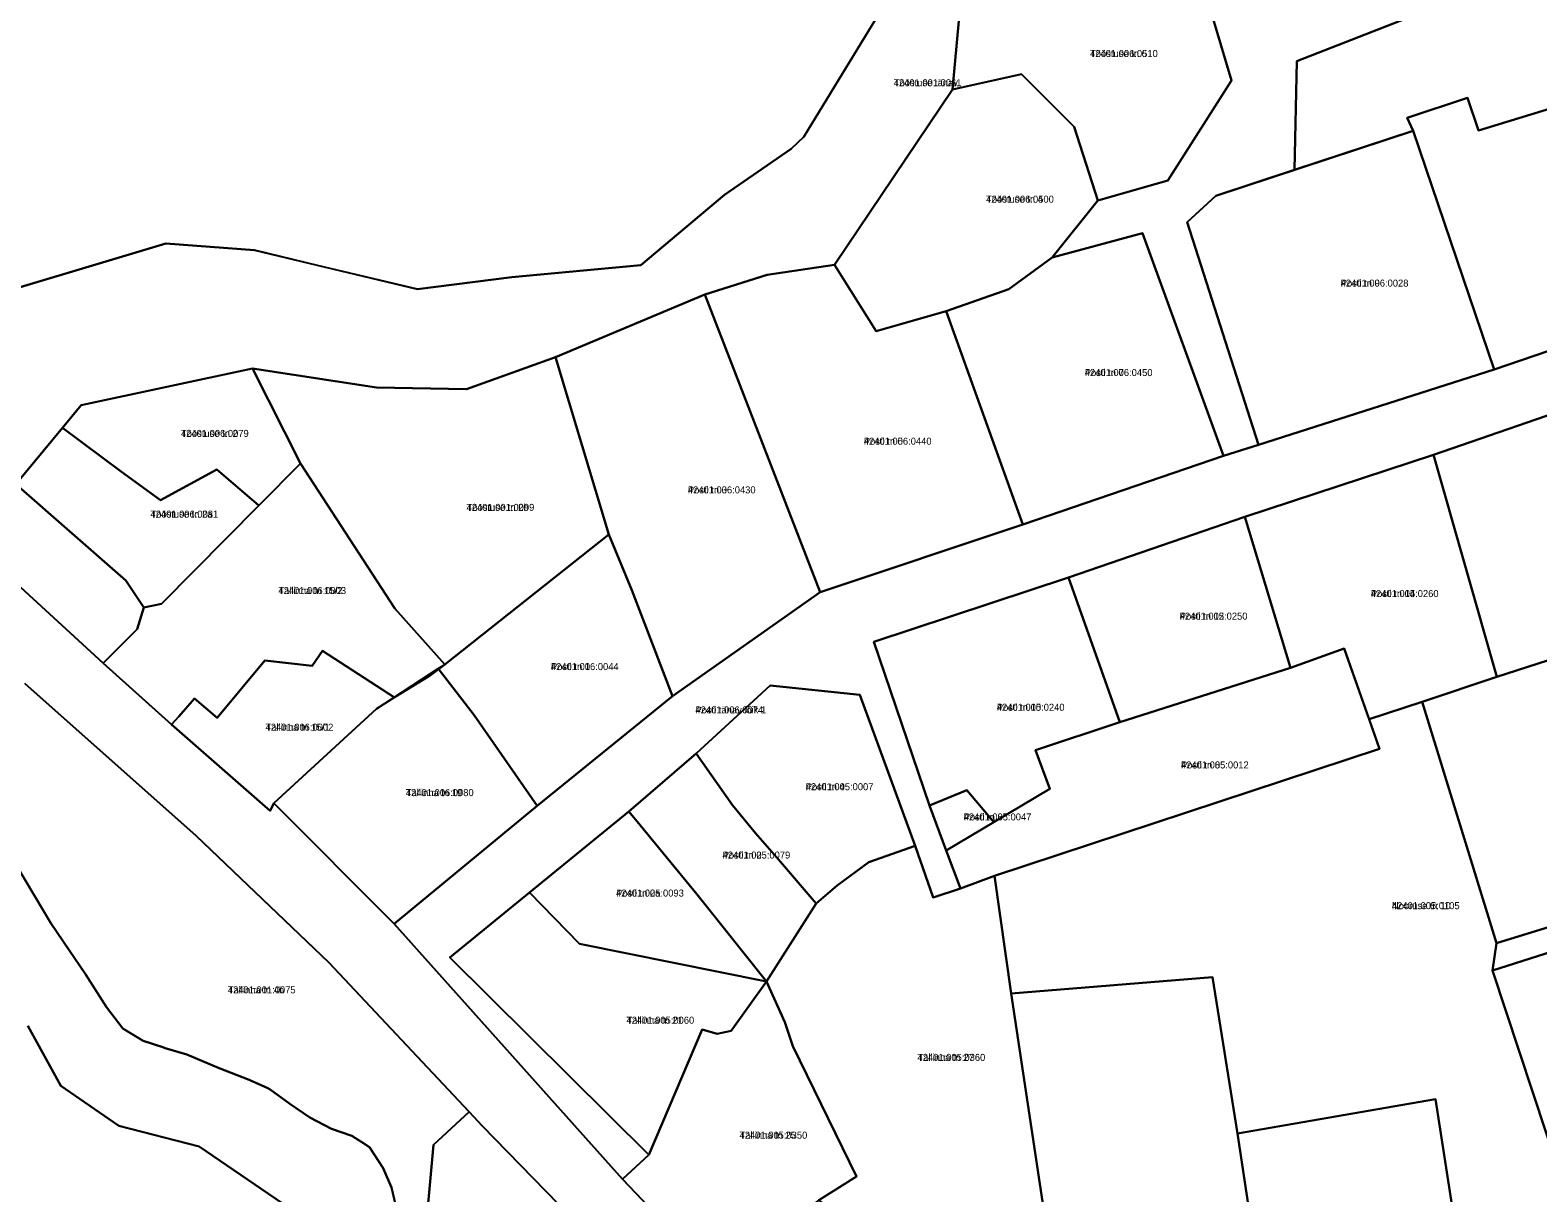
# Model space of a CAD drawing. Extents: x 595979 to 597983, y 6604231 to 6607350.
# Drawn here: x 596873.6 to 597196.3, y 6606309.2 to 6606558.1 of the extents above; entities that cross this region are included whole.
import ezdxf

# ---------------------------------------------------------------- set-up
doc = ezdxf.new("R2010")
doc.units = 0
for name, color, linetype in [('L_AADRESS', 7, 'Continuous'), ('PIIR', 7, 'Continuous'), ('TUNNUS', 7, 'Continuous')]:
    doc.layers.add(name, color=color, linetype=linetype)

msp = doc.modelspace()

# ---------------------------------------------------------------- linework, layer by layer
at = {"layer": 'PIIR'}
for points in [[(597099.55, 6606577.35), (597115.61, 6606582.36), (597120.15, 6606583.09), (597130.78, 6606547.35), (597117.1, 6606525.95), (597102.13, 6606521.61), (597097.06, 6606537.41), (597085.79, 6606548.69), (597071.01, 6606545.43), (597072.92, 6606565.63)], [(597054.66, 6606493.63), (597045.75, 6606507.88), (597071.01, 6606545.43), (597085.79, 6606548.69), (597097.06, 6606537.41), (597102.13, 6606521.61), (597092.39, 6606509.42), (597083.11, 6606502.64), (597069.66, 6606497.95)], [(597168.37, 6606539.36), (597181.28, 6606543.65), (597183.62, 6606536.59), (597214.68, 6606546.12), (597230.22, 6606500.23), (597187.03, 6606485.44), (597169.62, 6606536.56)], [(597121.24, 6606517.02), (597127.39, 6606522.61), (597169.62, 6606536.56), (597187.03, 6606485.44), (597136.51, 6606469.35)], [(597069.66, 6606497.95), (597083.11, 6606502.64), (597092.39, 6606509.42), (597111.7, 6606514.64), (597129.04, 6606466.93), (597086.11, 6606452.25)], [(597017.99, 6606501.53), (597031.35, 6606505.75), (597045.75, 6606507.88), (597054.66, 6606493.63), (597069.66, 6606497.95), (597086.11, 6606452.25), (597042.69, 6606437.76)], [(596986.06, 6606488.07), (597017.99, 6606501.53), (597042.69, 6606437.76), (597011.11, 6606415.53), (597002.42, 6606438.22), (596997.47, 6606450.15)], [(596962.32, 6606422.28), (596951.65, 6606434.3), (596931.47, 6606465.29), (596921.16, 6606485.69), (596947.7, 6606481.62), (596966.99, 6606481.22), (596986.06, 6606488.07), (596997.47, 6606450.15)], [(596921.16, 6606485.69), (596931.47, 6606465.29), (596922.57, 6606456.35), (596913.52, 6606464.07), (596901.5, 6606457.46), (596893.16, 6606463.53), (596880.53, 6606472.99), (596884.49, 6606477.81)], [(597174.04, 6606467.2), (597212.02, 6606480.33), (597221.77, 6606454.36), (597228.92, 6606432.96), (597187.57, 6606419.63)], [(596880.53, 6606472.99), (596893.16, 6606463.53), (596901.5, 6606457.46), (596913.52, 6606464.07), (596922.57, 6606456.35), (596901.72, 6606435.27), (596897.91, 6606434.49), (596894.03, 6606440.25), (596870.54, 6606460.92)], [(596896.52, 6606429.86), (596897.91, 6606434.49), (596901.72, 6606435.27), (596922.57, 6606456.35), (596931.47, 6606465.29), (596951.65, 6606434.3), (596962.32, 6606422.28), (596958.9, 6606419.7), (596951.59, 6606415.2), (596936.16, 6606425.24), (596933.93, 6606421.99), (596923.84, 6606423.15), (596913.65, 6606410.88), (596908.76, 6606415.01), (596905.41, 6606411.12), (596903.83, 6606409.45), (596889.22, 6606422.58)], [(597133.6, 6606453.87), (597174.04, 6606467.2), (597187.57, 6606419.63), (597171.57, 6606414.32), (597160.2, 6606410.55), (597154.86, 6606425.7), (597143.41, 6606421.57)], [(597095.9, 6606440.91), (597133.6, 6606453.87), (597143.41, 6606421.57), (597106.84, 6606409.91)], [(597002.42, 6606438.22), (597011.11, 6606415.53), (596982.09, 6606392.04), (596968.63, 6606411.41), (596960.9, 6606421.44), (596962.32, 6606422.28), (596997.47, 6606450.15)], [(597054.19, 6606427.13), (597095.9, 6606440.91), (597106.84, 6606409.91), (597088.79, 6606403.91), (597091.88, 6606395.67), (597079.85, 6606388.53), (597074.13, 6606395.36), (597066.13, 6606392.08)], [(597171.57, 6606414.32), (597187.57, 6606419.63), (597228.92, 6606432.96), (597235.02, 6606407.08), (597244.31, 6606380.13), (597187.46, 6606362.63)], [(597088.79, 6606403.91), (597106.84, 6606409.91), (597143.41, 6606421.57), (597154.86, 6606425.7), (597162.42, 6606404.24), (597080.06, 6606377.03), (597072.74, 6606374.35), (597069.68, 6606382.44), (597079.85, 6606388.53), (597091.88, 6606395.67)], [(596923.84, 6606423.15), (596933.93, 6606421.99), (596936.16, 6606425.24), (596951.59, 6606415.2), (596947.71, 6606412.81), (596925.76, 6606392.61), (596924.96, 6606390.98), (596903.83, 6606409.45), (596905.41, 6606411.12), (596908.76, 6606415.01), (596913.65, 6606410.88)], [(596925.76, 6606392.61), (596947.71, 6606412.81), (596960.9, 6606421.44), (596968.63, 6606411.41), (596982.09, 6606392.04), (596951.48, 6606366.75)], [(597016.19, 6606403.24), (597032.01, 6606417.81), (597051.18, 6606415.8), (597063.03, 6606383.44), (597053.14, 6606379.98), (597046.38, 6606375), (597041.83, 6606371.12), (597033.33, 6606381.07), (597028.87, 6606386.2), (597023.96, 6606392.2)], [(597080.06, 6606377.03), (597162.42, 6606404.24), (597160.2, 6606410.55), (597171.57, 6606414.32), (597187.46, 6606362.63), (597186.67, 6606356.79), (597201.01, 6606313.35), (597238.31, 6606326.16), (597250.13, 6606310.53), (597231.9, 6606292.55), (597234.92, 6606289.4), (597221.43, 6606274.46), (597196.48, 6606246.74), (597188.4, 6606239.05), (597174.43, 6606329.25), (597132.04, 6606321.84), (597126.69, 6606355.35), (597083.62, 6606351.85)], [(597001.77, 6606390.83), (597016.19, 6606403.24), (597023.96, 6606392.2), (597028.87, 6606386.2), (597033.33, 6606381.07), (597041.83, 6606371.12), (597031.22, 6606354.38), (597016.3, 6606373.12), (597004.16, 6606387.92)], [(597066.13, 6606392.08), (597074.13, 6606395.36), (597079.85, 6606388.53), (597069.68, 6606382.44)], [(596980.51, 6606373.46), (597001.77, 6606390.83), (597004.16, 6606387.92), (597016.3, 6606373.12), (597018.59, 6606370.24), (597031.22, 6606354.38), (596991.15, 6606362.47)], [(597186.67, 6606356.79), (597296.9, 6606391.91), (597320.66, 6606372.05), (597305.91, 6606350.72), (597286.26, 6606343.26), (597250.13, 6606310.53), (597238.31, 6606326.16), (597201.01, 6606313.35)], [(597041.83, 6606371.12), (597046.38, 6606375), (597053.14, 6606379.98), (597063.03, 6606383.44), (597066.89, 6606372.38), (597072.74, 6606374.35), (597080.06, 6606377.03), (597083.62, 6606351.85), (597095.88, 6606270.34), (597042.44, 6606307.62), (597050.51, 6606312.65), (597036.88, 6606340.6), (597035.11, 6606345.68), (597031.22, 6606354.38)], [(596963.43, 6606359.52), (596980.51, 6606373.46), (596991.15, 6606362.47), (597031.22, 6606354.38), (597023.67, 6606343.83), (597020.65, 6606343.19), (597017.42, 6606344.12), (597006.05, 6606317.27)], [(597017.42, 6606344.12), (597020.65, 6606343.19), (597023.67, 6606343.83), (597031.22, 6606354.38), (597035.11, 6606345.68), (597036.88, 6606340.6), (597050.51, 6606312.65), (597042.44, 6606307.62), (597020.14, 6606291.3), (597000.4, 6606312.1), (597006.05, 6606317.27)], [(597083.62, 6606351.85), (597126.69, 6606355.35), (597132.04, 6606321.84), (597144.75, 6606237.64), (597095.88, 6606270.34)], [(597174.43, 6606329.25), (597188.4, 6606239.05), (597184.43, 6606225.56), (597184.95, 6606218.63), (597174.17, 6606217.61), (597144.75, 6606237.64), (597132.04, 6606321.84)], [(596992.17, 6606301.13), (596951.96, 6606258.85), (596947.69, 6606263.93), (596954.68, 6606275.37), (596957.88, 6606296.75), (596959.9, 6606319.46), (596967.59, 6606326.51), (596970.33, 6606323.53)]]:
    msp.add_lwpolyline(points, close=True, dxfattribs=at)
for points in [[(597187.35, 6606568.17), (597144.75, 6606551.47), (597144.22, 6606528.17), (597127.39, 6606522.61), (597121.24, 6606517.02), (597136.51, 6606469.35), (597129.04, 6606466.93), (597111.7, 6606514.64), (597092.39, 6606509.42), (597102.13, 6606521.61), (597117.1, 6606525.95), (597130.78, 6606547.35), (597120.15, 6606583.09)], [(597253.73, 6606583.05), (597260.71, 6606540.89), (597268.29, 6606513.24), (597263.96, 6606511.51), (597249.66, 6606556.3), (597214.68, 6606546.12), (597183.62, 6606536.59), (597181.28, 6606543.65), (597168.37, 6606539.36), (597169.62, 6606536.56), (597144.22, 6606528.17), (597144.75, 6606551.47), (597187.35, 6606568.17)], [(597072.92, 6606565.63), (597071.01, 6606545.43), (597045.75, 6606507.88), (597031.35, 6606505.75), (597017.99, 6606501.53), (596986.06, 6606488.07), (596966.99, 6606481.22), (596947.7, 6606481.62), (596921.16, 6606485.69), (596884.49, 6606477.81), (596880.53, 6606472.99), (596870.54, 6606460.92), (596894.03, 6606440.25), (596897.91, 6606434.49), (596896.52, 6606429.86), (596889.22, 6606422.58), (596834.39, 6606472.9)], [(597055.58, 6606562.03), (597039.22, 6606535.24), (597036.49, 6606532.69), (597022.2, 6606522.86), (597004.3, 6606507.78), (596976.72, 6606505.25), (596956.47, 6606502.63), (596935.36, 6606507.68), (596921.63, 6606511), (596902.6, 6606512.44), (596855.64, 6606498.37)], [(596855.64, 6606498.37), (596902.6, 6606512.44), (596921.63, 6606511), (596956.47, 6606502.63), (596976.72, 6606505.25), (597004.3, 6606507.78), (597022.2, 6606522.86), (597036.49, 6606532.69), (597039.22, 6606535.24), (597055.58, 6606562.03)], [(597212.02, 6606480.33), (597174.04, 6606467.2), (597133.6, 6606453.87), (597095.9, 6606440.91), (597054.19, 6606427.13), (597066.13, 6606392.08), (597069.68, 6606382.44), (597072.74, 6606374.35), (597066.89, 6606372.38), (597063.03, 6606383.44), (597051.18, 6606415.8), (597032.01, 6606417.81), (597016.19, 6606403.24), (597001.77, 6606390.83), (596980.51, 6606373.46), (596963.43, 6606359.52), (597006.05, 6606317.27), (597000.4, 6606312.1), (596951.48, 6606366.75), (596982.09, 6606392.04), (597011.11, 6606415.53), (597042.69, 6606437.76), (597086.11, 6606452.25), (597129.04, 6606466.93), (597136.51, 6606469.35), (597187.03, 6606485.44), (597230.22, 6606500.23)], [(597441.43, 6606253.64), (597413.23, 6606283.67), (597400.46, 6606298.74), (597369.25, 6606325.59), (597373.25, 6606330.04), (597351.53, 6606347.3), (597320.66, 6606372.05), (597296.9, 6606391.91), (597186.67, 6606356.79), (597187.46, 6606362.63), (597244.31, 6606380.13), (597284.55, 6606394.16), (597277.83, 6606420.62), (597261.05, 6606466.64), (597252.65, 6606493), (597267.39, 6606497.51), (597276.42, 6606470.77), (597290.63, 6606426.26), (597303.29, 6606392.45), (597308.82, 6606394.53), (597405, 6606315.04), (597418.56, 6606303.86), (597449.96, 6606275.13)], [(596834.39, 6606472.9), (596889.22, 6606422.58), (596903.83, 6606409.45), (596924.96, 6606390.98), (596925.76, 6606392.61), (596951.48, 6606366.75), (597000.4, 6606312.1), (597020.14, 6606291.3), (597023.9, 6606287.2), (597033.87, 6606277.01), (597046.17, 6606265.47), (597068.29, 6606249.61), (597082.64, 6606237.21), (597106.96, 6606216.02), (597116.23, 6606207.98), (597135.48, 6606190.61), (597151.62, 6606177.02), (597172.5, 6606162.53), (597181.22, 6606157.49), (597190.5, 6606152.27), (597213.06, 6606142.48)], [(596872.46, 6606418.2), (596909.1, 6606385.61), (596937.54, 6606358.48), (596967.59, 6606326.51), (596959.9, 6606319.46), (596957.88, 6606296.75)], [(597335.48, 6606042.99), (597280.71, 6606085.45), (597282.61, 6606087.75), (597275.71, 6606093.22), (597238.19, 6606110.46), (597218.63, 6606121.93), (597177.93, 6606140.7), (597164.82, 6606146.62), (597140.63, 6606166.31), (597143.65, 6606169.64), (597122.43, 6606187.25), (597115.38, 6606188.24), (597077.86, 6606221.72), (597054.46, 6606238.34), (597030.62, 6606259.83), (597027.93, 6606264.63), (597023.69, 6606268.92), (597012.28, 6606280.57), (596992.17, 6606301.13), (596970.33, 6606323.53), (596967.59, 6606326.51), (596937.54, 6606358.48), (596909.1, 6606385.61), (596872.46, 6606418.2)], [(596953.65, 6606298.71), (596950.93, 6606310.3), (596949.18, 6606314.44), (596946.25, 6606318.94), (596944.59, 6606319.99), (596942.44, 6606321.37), (596938.1, 6606322.84), (596933.47, 6606325.28), (596929.16, 6606328.24), (596924.99, 6606331.3), (596924.48, 6606331.54), (596920.45, 6606333.34), (596914.02, 6606335.85), (596907.1, 6606338.81), (596902.47, 6606340.17), (596901.98, 6606340.33), (596897.79, 6606341.72), (596893.42, 6606344.37), (596889.94, 6606348.91), (596885.4, 6606355.99), (596881.95, 6606361.12), (596878.04, 6606366.93), (596874.63, 6606372.52), (596869.78, 6606380.71)], [(596869.78, 6606380.71), (596874.63, 6606372.52), (596878.04, 6606366.93), (596881.95, 6606361.12), (596885.4, 6606355.99), (596889.94, 6606348.91), (596893.42, 6606344.37), (596897.79, 6606341.72), (596901.98, 6606340.33), (596902.47, 6606340.17), (596907.1, 6606338.81), (596914.02, 6606335.85), (596920.45, 6606333.34), (596924.48, 6606331.54), (596924.99, 6606331.3), (596929.16, 6606328.24), (596933.47, 6606325.28), (596938.1, 6606322.84), (596942.44, 6606321.37), (596944.59, 6606319.99), (596946.25, 6606318.94), (596949.18, 6606314.44), (596950.93, 6606310.3), (596953.65, 6606298.71)], [(596873.07, 6606344.89), (596880.13, 6606332.1), (596892.53, 6606323.5), (596909.78, 6606319.05), (596932, 6606303.91), (596933.31, 6606285.77), (596921.98, 6606268.12), (596908.32, 6606251.69), (596904.39, 6606234.77), (596898.95, 6606216.64), (596891.77, 6606209.88), (596893.14, 6606173.15), (596936.13, 6606135.39), (596935.06, 6606090.99), (596994.79, 6606027), (597030.56, 6606083.77), (597045.82, 6606076.48), (597057.63, 6606074.35), (597071.17, 6606067.83), (597079.05, 6606055.73), (597083.05, 6606050.71), (597087.59, 6606045.02)], [(596932, 6606303.91), (596909.78, 6606319.05), (596892.53, 6606323.5), (596880.13, 6606332.1), (596873.07, 6606344.89)]]:
    msp.add_lwpolyline(points, dxfattribs=at)

# ---------------------------------------------------------------- texts
at = {"layer": 'L_AADRESS'}
for s, p in [('Tööstuse tn 6', (597100.48, 6606552.35)), ('Tööstuse tänav', (597058.46, 6606546.1)), ('Tööstuse tn 4', (597078.23, 6606521.16)), ('Posti tn 9', (597154.14, 6606503.2)), ('Posti tn 7', (597099.35, 6606484.04)), ('Tööstuse tn 2', (596905.87, 6606471.02)), ('Posti tn 5', (597052.05, 6606469.34)), ('Posti tn 3', (597014.38, 6606458.92)), ('Tööstuse tn 2a', (596899.34, 6606453.74)), ('Tööstuse tn 2b', (596967.01, 6606455.18)), ('Tallinna tn 15/2', (596926.72, 6606437.37)), ('Posti tn 14', (597160.59, 6606436.72)), ('Posti tn 12', (597119.68, 6606431.89)), ('Posti tn 1', (596985.07, 6606421.09)), ('Posti tänav lõik 1', (597016, 6606411.81)), ('Posti tn 10', (597080.52, 6606412.38)), ('Tallinna tn 15/1', (596923.98, 6606408.11)), ('Posti tn 8', (597119.95, 6606400.03)), ('Posti tn 4', (597039.61, 6606395.37)), ('Tallinna tn 19', (596954.02, 6606394.1)), ('Posti tn 6', (597073.42, 6606388.9)), ('Posti tn 2', (597021.8, 6606380.74)), ('Posti tn 2a', (596999.02, 6606372.6)), ('Nooruse tn 10', (597165.1, 6606369.9)), ('Tallinna tn 4b', (596915.9, 6606351.87)), ('Tallinna tn 21', (597001.24, 6606345.37)), ('Tallinna tn 27', (597063.55, 6606337.42)), ('Tallinna tn 25', (597025.45, 6606320.76))]:
    msp.add_text(s, height=1.5, dxfattribs=at).set_placement(p)
at = {"layer": 'TUNNUS'}
for s, p in [('42401:006:0510', (597100.48, 6606552.35)), ('42401:001:0061', (597058.46, 6606546.1)), ('42401:006:0500', (597078.23, 6606521.16)), ('42401:006:0028', (597154.14, 6606503.2)), ('42401:006:0450', (597099.35, 6606484.04)), ('42401:006:0079', (596905.87, 6606471.02)), ('42401:006:0440', (597052.05, 6606469.34)), ('42401:006:0430', (597014.38, 6606458.92)), ('42401:006:0081', (596899.34, 6606453.74)), ('42401:001:0099', (596967.01, 6606455.18)), ('42401:006:0003', (596926.72, 6606437.37)), ('42401:005:0260', (597160.59, 6606436.72)), ('42401:005:0250', (597119.68, 6606431.89)), ('42401:006:0044', (596985.07, 6606421.09)), ('42401:006:0074', (597016, 6606411.81)), ('42401:005:0240', (597080.52, 6606412.38)), ('42401:006:0002', (596923.98, 6606408.11)), ('42401:005:0012', (597119.95, 6606400.03)), ('42401:005:0007', (597039.61, 6606395.37)), ('42401:006:0080', (596954.02, 6606394.1)), ('42401:005:0047', (597073.42, 6606388.9)), ('42401:005:0079', (597021.8, 6606380.74)), ('42401:005:0093', (596999.02, 6606372.6)), ('42401:005:0105', (597165.1, 6606369.9)), ('42401:001:0075', (596915.9, 6606351.87)), ('42401:005:0060', (597001.24, 6606345.37)), ('42401:005:0360', (597063.55, 6606337.42)), ('42401:005:0350', (597025.45, 6606320.76))]:
    msp.add_text(s, height=1.5, dxfattribs=at).set_placement(p)

doc.saveas('drawing.dxf')
